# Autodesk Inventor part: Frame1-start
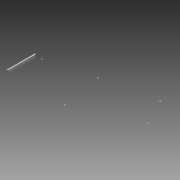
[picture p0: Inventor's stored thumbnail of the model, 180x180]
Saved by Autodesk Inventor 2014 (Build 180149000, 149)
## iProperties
Created: 2009-05
Part Number: Frame1-start
Document SubType Name: Modeling
Designer: millerpa
Density: 1 g/cm^3
Material: Generic
Appearance: Default
Author: millerpa
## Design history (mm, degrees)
derived "Skeleton-frame-start.ipt"
  workplane "Work Plane1"
  workplane "Work Plane2"
  workplane "Work Plane3"
  workplane "Work Plane4"
  workplane "Work Plane5"
  workplane "Work Plane6"
  sketch "Sketch2"
    geometry: L1 (-19.05, -44.45)-(19.05, -44.45) reference; L2 (19.05, -44.45)-(19.05, 44.45) reference; L3 (19.05, 44.45)-(-19.05, 44.45) reference; L4 (-19.05, 44.45)-(-19.05, -44.45) reference; 2 further points
extrude "Extrusion2" new body sketch "Sketch2" stored distance "d11" = 10; taper "d22" = 0 deg
body "Solid2"
feature "Srf1::Skeleton-frame-start.ipt"
body "Srf1"
feature "Srf6::Skeleton-frame-start.ipt"
body "Srf3"
other parameters: "d52" = 45 deg, "d53" = 45 deg, "d0_1" = 3772.27615, "d1" = 914.4, "d2" = 1662.8558, "d26" = 38.1, "d27" = 88.9, "d28" = 19.05, "d29" = 44.45, "d30" = 76.2, "d31" = 127, "d32" = 38.1, "d33" = 88.9, "d34" = 19.05, "d35" = 44.45, "d36" = 76.2, "d37" = 127, "d38" = 38.1, "d39" = 88.9, "d40" = 19.05, "d41" = 44.45, "d42" = 76.2, "d43" = 127, "d44" = 38.1, "d45" = 88.9, "d46" = 19.05, "d47" = 44.45, "d48" = 76.2, "d49" = 127, "d3" = 14.25776, "d5" = 14.25776, "d7" = 14.25776, "d8" = 14.25776, "d9" = 304.8, "d10" = 304.8, "FrameW" = 38.1, "FrameH" = 88.9, "d12" = 38.1, "d13" = 88.9, "d14" = 19.05, "d15" = 44.45, "d16" = 38.1, "d17" = 88.9, "d18" = 19.05, "d19" = 44.45, "d20" = 76.2, "d21" = 127
